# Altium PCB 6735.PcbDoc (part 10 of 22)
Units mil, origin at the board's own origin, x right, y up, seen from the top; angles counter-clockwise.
Board outline 2641.73 x 5165.35 mil, 6 copper layers (Top, Inner Layer 2, Inner Layer 3, Inner Layer 4, Inner Layer 5, Bottom), stack 35.7 mil thick; 1011 components, 790 nets, 4118 pads, 9325 vias.
Unrouted connection lines stored in the file: 4610.
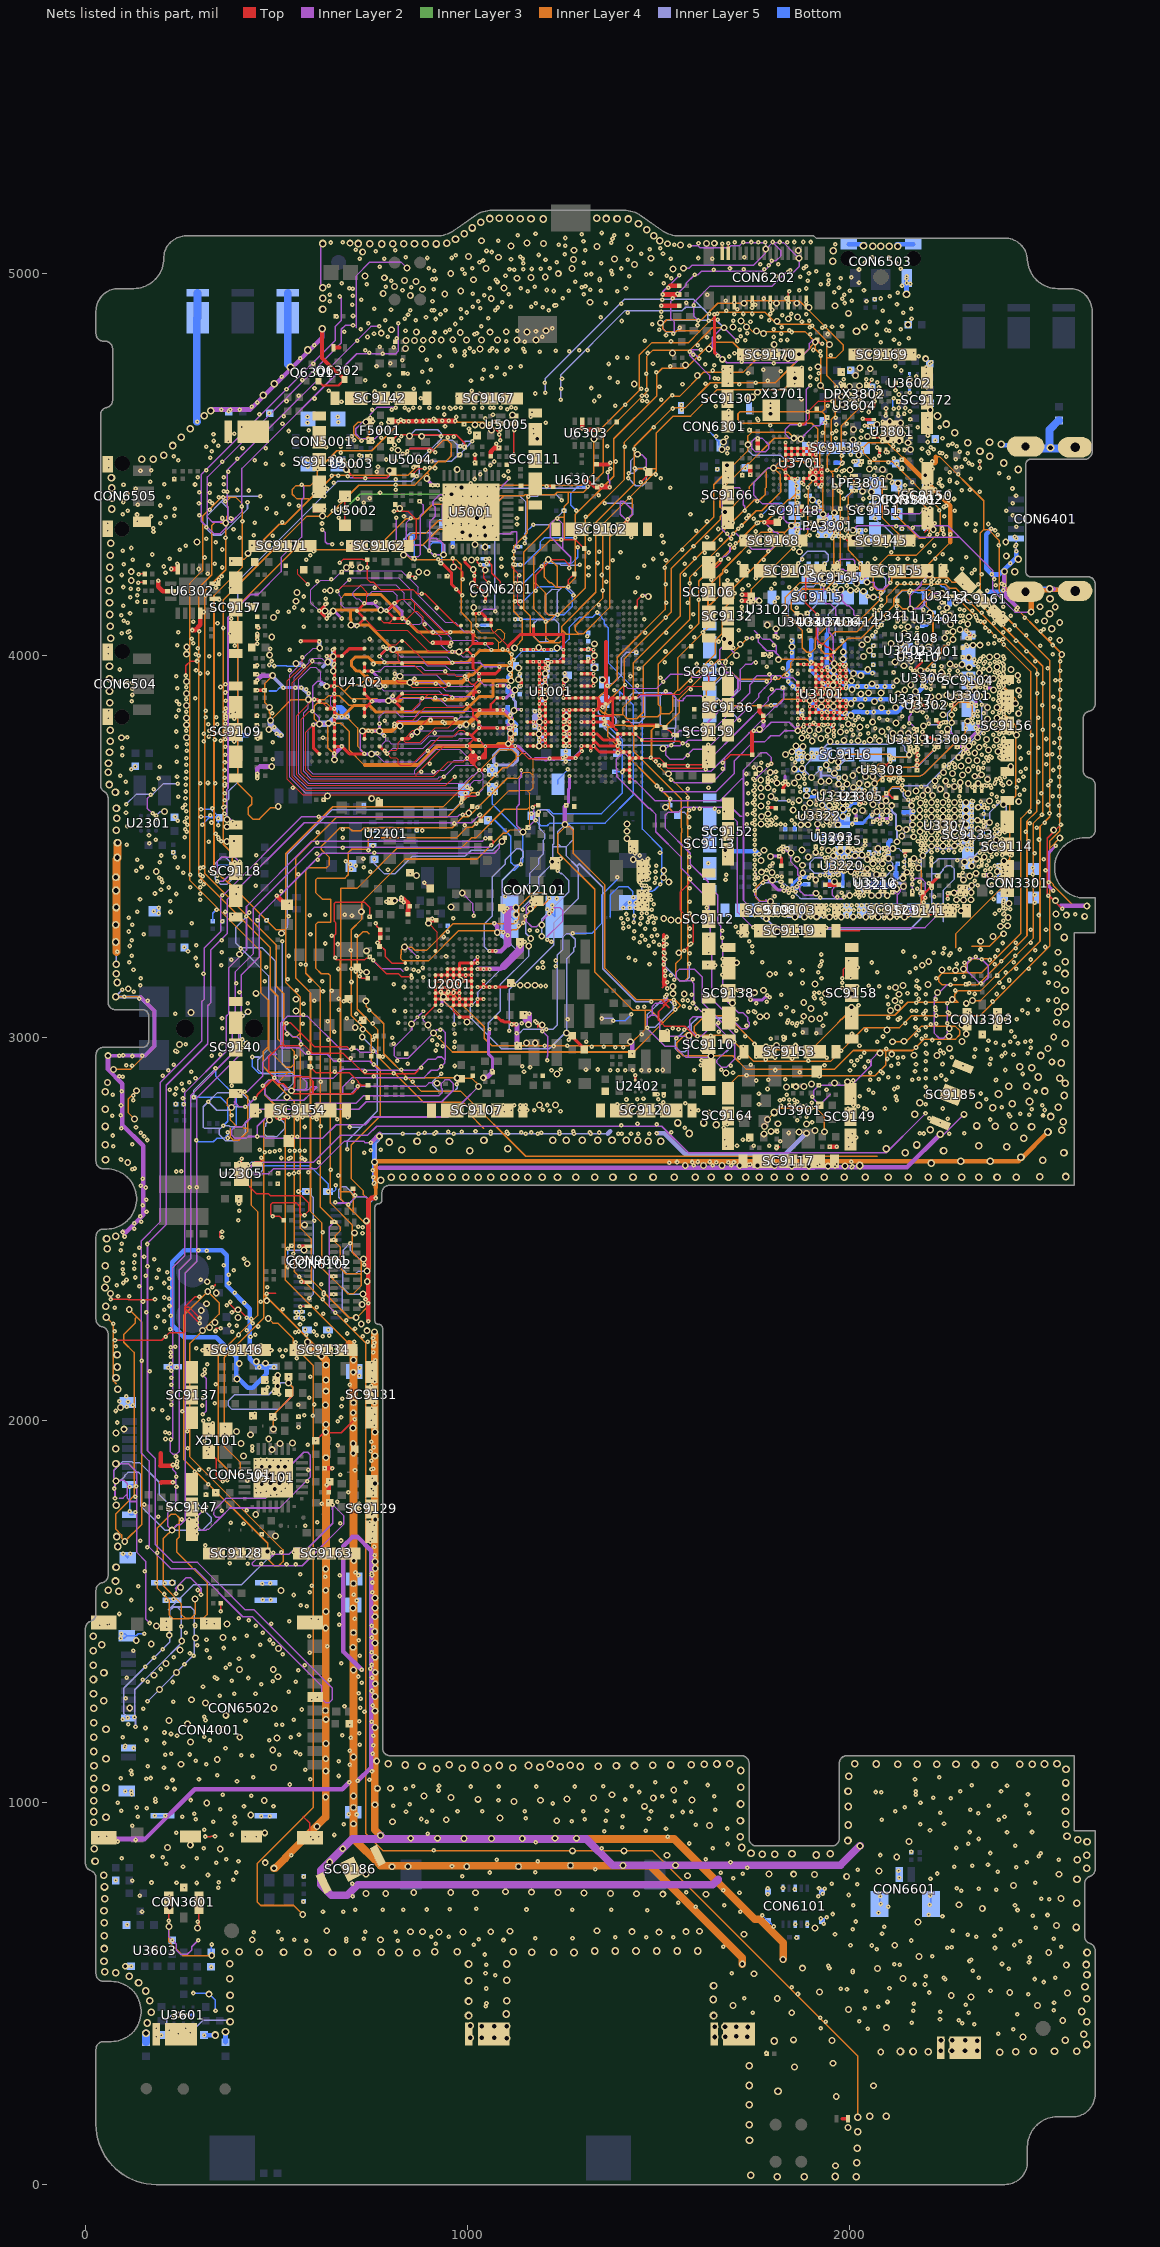
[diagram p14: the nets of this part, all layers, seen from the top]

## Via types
v1: diameter 12, hole 4, Top to Inner Layer 2, 3329 vias
v2: diameter 12, hole 4, Inner Layer 5 to Bottom, 3071 vias
v3: diameter 18, hole 10, Inner Layer 2 to Inner Layer 5, 1928 vias
v4: diameter 10, hole 4, Top to Inner Layer 2, 525 vias
v5: diameter 20, hole 12, Top to Bottom, 472 vias

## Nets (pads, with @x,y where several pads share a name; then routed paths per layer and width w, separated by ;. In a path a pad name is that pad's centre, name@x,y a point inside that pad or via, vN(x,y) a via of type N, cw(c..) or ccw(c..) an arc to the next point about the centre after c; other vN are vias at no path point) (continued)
D_GND: (continued)
  Inner Layer 5 w4: v5(79.09,3107.9) 85.95,3107.9 85.95,3115.49 v2(95.95,3125.49) ; v5(80.31,3193.09) 80.31,3225.09 v2(83.31,3225.09) ; v2(106.31,3611.09) 133.31,3638.09 176.9,3638.09 204.15,3665.34 v2(241.42,3665.34) ; v2(110.95,1221.49) 99.95,1232.49 99.95,1298.6 219.95,1418.6 219.95,1500.94 ; v2(130.95,1197.49) 130.95,1222.49 128.95,1224.49 128.95,1294.72 172.82,1338.59 204.35,1370.12 240.13,1405.91 v3@250.31,1416.09 ; 155.36,2955.09 172.31,2972.04 ; v2(162.31,1264.09) 284.31,1386.09 284.31,1502.3 275.53,1511.09 230.1,1511.09 229.5,1510.49 ; v2(184.64,3581.19) 195.54,3592.09 v3(206.74,3592.09) ; v2(231.3,443.09) 225.13,443.09 212.31,430.27 212.31,413.08 223.3,402.09 279.3,402.09 307.3,430.09 378.3,430.09 v5(378.3,426.09) ; v3(251.92,1422.19) v3@250.31,1416.09 ; v2(283.71,2844.49) 283.71,2863.49 v2(340.31,2920.09) ; v3(366.95,4346.83) 368.95,4344.83 369.31,4345.09 372.31,4348.09 372.31,4386.3 355.26,4403.35 ; v3(369.96,3571.8) 369.96,3620.59 375.15,3625.77 375.15,3645.8 398.95,3669.61 398.95,4195.73 659.31,4456.09 852.31,4456.09 872.95,4476.73 v2(872.95,4509.49) 904.31,4540.85 ; v2@417.13,2816.09 413.13,2820.09 378.37,2820.09 v3(381.73,2818.12) 377.88,2818.12 377.88,2810.7 343.7,2810.7 v2(321.31,2833.09) ; v2(420.81,3318.15) 422.99,3318.59 421.69,3317.28 392.95,3288.54 392.95,3248.31 404.95,3236.31 ; v3(422.94,2984.48) 405.32,3002.1 405.32,3048.86 v3(424.95,3068.48) ; v2(423.95,4401.83) 423.95,4384.17 355.61,4315.83 332.74,4315.83 318.95,4329.62 318.95,4367.04 355.26,4403.35 ; v2(436.31,2950.09) 454.41,2950.09 456.31,2948.19 ; v2(456.95,4416.83) 368.74,4416.83 355.26,4403.35 ; v2(464.31,2875.09) 470.31,2869.09 470.31,2852.09 485.31,2837.09 497.39,2837.09 521.48,2861.18 521.48,2870.09 ; v3(479.71,3807.09) 479.14,3806.71 479.14,3805.53 490.91,3805.53 v2(500.12,3796.33) ; v3(481.19,2784.95) 471.86,2775.62 471.86,2769.81 467.31,2765.26 467.31,2750.14 476.36,2741.09 499.53,2741.09 521.31,2762.88 521.31,2775.84 v2(508.17,2788.98) ; v2(491.79,1652.61) 409.01,1569.83 283.19,1569.83 217.12,1503.76 219.95,1500.94 ; v3(513.14,3273.68) 528.17,3288.7 528.17,3295.67 529.77,3297.27 529.77,3314.67 529.22,3315.22 527.43,3317.01 527.43,3318.01 v2@527.53,3318.01 ; v2(515.1,3252.49) 515.1,3114.08 514.95,3113.94 514.95,2932.62 544.24,2903.33 544.24,2881.91 532.43,2870.09 521.48,2870.09 ; v2(529.72,2448.27) 532.94,2445.05 v3(572.13,2445.05) ; v2(532.01,3318.01) v2@527.53,3318.01 ; v2(579.64,2598.19) 596.31,2581.52 596.31,2329.85 585.43,2318.97 v2(585.31,2319.09) ; v2(684.95,2708.83) 684.95,2730.47 721.31,2766.83 ; v2(690.95,2766.83) 721.31,2766.83 ; v3(708.31,2268.09) 689.89,2268.09 672.08,2285.9 672.08,2350.57 673.6,2352.09 ; v3(724.31,3002.09) 763.95,2962.45 763.95,2809.47 721.31,2766.83 ; v3(725.91,2329.63) 690.33,2329.63 673.6,2346.36 673.6,2352.09 ; v3(727.81,2421.25) 716.81,2421.25 692.25,2445.81 v2(692.25,2463.09) 675.08,2445.92 675.08,2411.09 ; v3(734.82,2521.43) 744.31,2530.92 744.31,2568.09 748.31,2572.09 ; v3(736.3,2390.09) 714.29,2390.09 707.29,2383.09 683.89,2383.09 675.08,2391.9 675.08,2411.09 ; v2(755.95,3467.83) 755.95,3455.45 781.34,3430.06 810.31,3430.06 855.31,3475.06 993.31,3475.06 1009.34,3491.09 1065.21,3491.09 1084.44,3510.32 1085.12,3509.65 1089.35,3513.87 v3(1089.69,3513.53) ; v3(832.31,4263.09) 832.31,4283.09 v2(833.31,4283.09) ; v3(847.52,4574.76) 847.39,4575.11 863.37,4591.09 921.59,4591.09 931.31,4581.36 931.31,4567.85 904.31,4540.85 ; v2(905.31,4509.09) 958.62,4509.09 972.56,4523.03 972.56,4551.97 961.44,4563.09 934.31,4563.09 909.24,4538.02 907.14,4538.02 904.31,4540.85 ; v2(930.31,4409.09) 936.91,4402.49 938.95,4402.49 ; v2(930.64,2906.24) 920.86,2896.46 919.27,2896.46 908.7,2885.88 908.7,2876.77 925.38,2860.09 964.31,2860.09 972.54,2868.32 v3(972.54,2895.04) ; v3(936.9,3107.5) 936.9,3097.07 965.31,3068.66 v2(965.31,3035.09) ; v2(980.06,4527.5) 996.17,4543.61 996.17,4544.78 v2(1012.28,4560.88) 993.45,4560.88 v2(980.06,4547.5) ; v2(982.91,4340.77) 978.22,4336.09 927.31,4336.09 908.31,4317.09 ; v2(982.95,3616.49) 963.86,3597.4 645.77,3597.4 631.48,3583.11 527.43,3479.05 527.43,3332.95 527.53,3332.84 v2@527.53,3318.01 ; v3(1043.31,4336.09) 1043.31,4357.09 1053.31,4367.09 1053.31,4406.09 1085.31,4438.09 1314.31,4438.09 v2(1314.31,4442.68) ; v2(1071.78,4116.16) 1071.31,4114.87 1071.31,4395.3 1094.1,4418.09 1136.53,4418.09 1152.31,4402.3 1152.31,4291.72 1151.03,4294.85 v2(1149.86,4294.71) ; v2(1109.31,3019.09) 1109.31,3127.22 1225.31,3243.22 1225.31,3300.56 1288.95,3364.2 1288.95,3445.45 1285.31,3449.09 ; v2(1127.95,3011.83) 1127.95,3013.09 1135.98,3013.09 1144.98,3022.09 1222.31,3022.09 1234.31,3034.09 v2@1234.31,3184.09 ; v2@1141.25,3452.09 1141.25,3452.53 v2(1138.95,3454.83) ; v2(1144.01,3336.07) 1144.01,3341.09 1185.95,3383.03 1185.95,3420.13 1219.42,3453.6 v3@1219.42,3453.71 ; v2(1158.16,4416.07) 1164.31,4417.09 1182.31,4417.09 1186.31,4421.09 1232.31,4421.09 v2(1246.31,4407.09) ; v3(1159.95,3240.83) 1160.31,3240.47 1160.31,3214.4 1085.31,3139.4 1085.31,3070.29 1053.48,3038.46 1053.48,3007.09 ; v3(1164.95,3259.83) 1164.95,3260.83 1151.95,3273.83 1151.95,3321.04 1177.74,3346.83 1197.16,3346.83 1214.69,3364.35 v2(1213.95,3365.09) ; v2(1171.95,4342.83) 1214.7,4342.83 1236.37,4364.5 1236.62,4364.5 v2(1251.95,4379.83) ; v3(1193.95,3265.83) v3(1193.95,3295.83) 1193.95,3310.88 1264.12,3381.04 1264.12,3412.58 1246.54,3430.16 1242.98,3430.16 v2(1236,3437.13) v3@1219.42,3453.71 ; v2(1202.95,4687.83) 1202.95,4725.15 1410.89,4933.09 1590.45,4933.09 1611.71,4911.83 ; v2(1203.77,4089.21) v2@1203.95,4089.02 ; v3(1210.95,4251.83) 1215.18,4251.83 1223.92,4243.09 1224.44,4243.09 1225.44,4242.09 1225.91,4242.09 1227.61,4240.39 1239.97,4240.39 1243.93,4236.43 1293.16,4236.43 v2(1293.16,4238.23) ; v3(1221.25,3460.92) v3@1222.31,3457.53 ; 1221.44,4173.97 1220.73,4173.97 1203.62,4157.32 1203.62,4115.09 1211.88,4106.83 v2(1234.95,4106.83) 1234.95,4167.61 1241.31,4173.97 1245.88,4178.54 1262.86,4178.54 1277.31,4164.09 1277.31,4163.39 v2(1276.8,4158.33) ; v2(1230.19,3187.79) 1230.03,3187.79 1230.03,3186.09 1232.31,3186.09 v2@1234.31,3184.09 ; v2(1243.95,4669.83) 1243.95,4735.04 1411.75,4902.83 1561.62,4902.83 1570.62,4911.83 1611.71,4911.83 ; v3(1258.95,3012.83) 1256.04,3012.83 v3@1255.37,3013.51 ; v2(1262.31,3049.09) 1261.31,3050.09 v2@1258.95,3050.09 ; v2(1350.96,3050.69) 1350.96,3051.09 1380.31,3051.09 1381.31,3050.09 v2(1381.31,3045.09) ; v3(1352.64,3936.03) 1361.58,3927.09 1379.79,3927.09 1401.31,3948.62 1401.31,3994.09 1416.31,4009.09 v2(1441.31,4009.09) ; v2(1353.95,3865.49) 1360.47,3865.49 1372.56,3877.59 1372.56,3889.89 1363.45,3899 1350.06,3899 1341.95,3890.89 1341.95,3849.49 v2(1355.95,3835.49) 1365.55,3845.09 1378.31,3845.09 1388.08,3835.32 1388.08,3822.89 1379.27,3814.09 1363.35,3814.09 v2(1356.95,3820.49) 1356.95,3811.45 v2(1396.31,3772.09) 1396.31,3766.09 v2(1532.31,3766.09) 1542.31,3776.09 1542.31,3810.09 ; v2(1358.95,4398.83) 1429.31,4398.83 1432.31,4395.83 1432.31,4369.81 1417.03,4354.53 1415.65,4354.53 v2(1403.95,4342.83) ; 1366.49,2749.09 1192.87,2749.09 775.3,2749.09 v3(768.88,2742.68) 768.88,2731.38 760.31,2722.81 760.31,2584.09 748.31,2572.09 ; v2(1419.95,4464.83) 1439.95,4444.83 1456.94,4444.83 1467.43,4455.32 1467.43,4491.83 1465.43,4489.83 1446.31,4489.83 1434.31,4477.83 v2(1420.95,4477.83) 1426.31,4483.19 1426.31,4509.1 v3(1444.2,4526.99) ; v2(1434.31,3303.09) 1434.31,3309.09 1435.31,3310.09 v2(1435.31,3319.09) ; v2(1454.95,3382.49) v2(1454.95,3399.49) ; v2(1479.98,3094.45) 1439.64,3094.45 1353.31,3180.78 1353.31,3394.09 1291.81,3455.59 1285.31,3449.09 ; v2(1516.31,3206.09) 1516.31,3187.75 1554.98,3149.09 1570.57,3149.09 1579.95,3158.47 v2(1579.95,3193.83) ; v2(1518.15,3906.9) 1512.92,3903.09 ; v2(1529.59,3625.13) 1529.59,3614.39 1529.25,3614.05 1529.25,3598.88 1538.04,3590.09 1547.69,3590.09 1547.95,3589.83 1567.57,3589.83 v2(1579.31,3578.09) ; v2(1554.95,4857.83) 1543.95,4846.83 1519.36,4846.83 1510.31,4855.87 1510.31,4870.19 1517.95,4877.83 v2@1627.95,4877.83 ; v2(1618.31,3068.09) 1617.66,3067.43 1623.31,3061.78 1623.31,3054.09 ; v2(1630.23,4876.11) v2@1627.95,4877.83 ; v2(1655.31,3039.09) 1655.31,3051.09 1656.31,3052.09 ; 1657.05,2954.81 1666.95,2954.81 ; v3(1670.31,4858.09) 1650.57,4877.83 1630.23,4877.83 v2@1627.95,4877.83 ; 1676.34,2963.56 1697.31,2984.54 v2(1697.31,2989.56) ; 1676.34,3052.09 1656.31,3052.09 ; v2(1710.65,3830.59) 1704.3,3836.94 1704.3,3838.28 1661.49,3881.09 ; v3(1733.31,4552.09) 1733.31,4537.71 1746.93,4524.09 1819.34,4524.09 1826.34,4517.09 1855.61,4517.09 1862.61,4510.09 v2(1888.3,4510.09) ; 1765.58,3358.09 1764.87,3358.09 1753.65,3369.31 1753.65,3386.59 v2(1772.65,3405.59) 1794.05,3405.59 1797.37,3408.91 v2(1817.67,3408.91) ; v3(1780.43,3418.88) 1781.36,3418.88 v3@1783.01,3417.23 ; v3(1781.4,3311.78) 1808.59,3284.59 2157.65,3284.59 2213.6,3340.53 2213.6,3429.41 ; v2(1782.65,3932.59) 1713.47,3932.59 1706.68,3939.38 ; v3(1791.99,3357.02) v3@1792.8,3357.83 ; v3@1794.65,3358.59 1793.56,3358.59 v3@1792.8,3357.83 ; v2(1807.59,3624.77) 1811.77,3620.59 1824.97,3620.59 1825.43,3620.13 v2(1840.46,3620.13) ; v2(1849.53,3391.68) 1858.44,3382.78 1858.44,3376.76 1869.41,3365.79 1870.25,3365.79 1871.51,3364.53 1873.01,3364.53 1873.95,3363.59 1982.05,3363.59 1991.38,3372.92 v3(1999.69,3372.92) ; v2(1865.17,4242.31) 1871.54,4248.67 1871.54,4255.53 1872.12,4256.12 1889.09,4273.09 1934.4,4273.09 1943.39,4264.1 1943.39,4249.15 v2(1934.31,4240.07) ; v3(1912.98,3316.79) v3@1914.47,3315.59 ; 1921.17,3312.5 1918.3,3312.5 v3@1914.47,3315.59 ; v2(1923.43,3703.69) 1913.19,3693.44 1912.54,3693.44 1900.17,3681.07 v3(1899.65,3681.59) 1883.65,3697.59 1883.65,3712.63 1897.24,3726.22 1898.65,3726.22 1941.03,3768.59 2104.65,3768.59 2111.65,3775.59 2128.94,3775.59 2144.06,3760.47 2144.06,3751.88 v3(2155.25,3740.69) 2150.15,3735.59 2112.36,3735.59 2106.36,3741.59 2002.6,3741.59 1968.18,3707.16 v2(1968.96,3706.38) ; 1924.65,3686.59 1948.65,3686.59 1954.65,3680.59 v2(1970.65,3680.59) ; v2(1932.64,4089.31) v2@1936.75,4088.23 ; v2(1943.11,4172.42) 1965.85,4172.42 1980.56,4157.71 1980.56,4145.29 1962.29,4127.02 1962,4127.02 1943.98,4109 1943.98,4095.45 v2@1936.75,4088.23 ; 1961.65,4051.59 1961.65,4082.09 v3@1965.32,4085.76 ; 1961.65,4089.06 v3@1962.02,4089.06 ; v2(1984.31,4411.09) 1985.53,4411.09 2008.31,4433.87 2008.31,4446.3 1989.53,4465.09 v2(1986.31,4465.09) ; 2010.34,3410.44 2022.42,3398.36 2027.69,3393.09 2102.83,3393.09 2117.7,3407.96 2132.99,3423.25 2144.69,3434.95 2144.69,3479.88 ; v3(2045.65,3442.59) v3@2045.65,3440.98 ; v3(2060.65,3455.59) 2044.32,3471.92 1908.7,3471.92 1895.65,3458.87 1895.65,3442.31 1907.37,3430.59 1967.38,3430.59 1974.38,3437.59 2031.26,3437.59 2034.65,3440.98 v3@2045.65,3440.98 ; v3(2061.65,4153.09) 2076.33,4153.09 2091.56,4168.32 2091.56,4180.5 2093.87,4182.8 2093.87,4201.61 v2(2080.57,4214.91) ; v2(2064.62,3650.43) 2064.62,3638.85 v3(2076.45,3627.03) 2076.45,3616.03 2079.59,3612.89 2086.36,3612.89 v3(2094.14,3620.67) ; v2(2065.81,4359.12) 2082.66,4342.28 2087.44,4342.28 2116.31,4313.4 2116.31,4278.09 ; v3@2104.87,3464.35 2112.74,3456.49 2112.74,3441.66 2091.02,3419.94 2052.58,3419.94 2045.65,3426.87 v3@2045.65,3440.98 ; v2@2104.87,3487.81 2104.87,3488.31 v3(2112.37,3495.81) ; v3(2109.65,3607.59) 2098.65,3618.59 2098.65,3638.18 2098.95,3638.48 2098.95,3640 2100.16,3641.21 2100.16,3641.73 2100.57,3642.14 2100.57,3642.44 2100.87,3642.74 2100.87,3643 2101.18,3643.31 2101.18,3643.66 2101.67,3644.15 2101.67,3644.89 2110.37,3653.59 2126.94,3653.59 ; v2(2132.9,4016.48) 2133.43,4016.48 2133.43,3999.71 v3(2133.96,3999.71) ; v3(2135.65,3528.59) 2157.65,3550.59 2157.65,3615.15 2139.65,3633.15 2139.65,3640.88 2126.94,3653.59 ; v3(2144.72,4096.17) 2122.81,4118.07 2122.81,4154.93 2138.29,4170.41 2151.73,4170.41 2155.81,4166.33 v2(2155.81,4165.65) ; v2(2149.46,3999.07) 2148.89,3998.5 v3@2160.65,3986.74 ; v2(2156.12,4014.27) 2156.12,4004.89 2160.65,4000.36 v3@2160.65,3986.74 ; 2177.36,3340.1 2152.85,3315.59 2073.67,3315.59 2025.65,3315.59 v3@1914.47,3315.59 ; v2(2183.65,3378.59) 2183.65,3387.59 2186.4,3390.34 2186.4,3470.34 2218.65,3502.59 2221.66,3499.59 2221.66,3499.27 2225.34,3495.59 2258.65,3495.59 2270.15,3495.59 2282.65,3508.09 2315.47,3508.09 2356.9,3549.52 2356.9,3555.31 v3(2365.38,3563.8) 2365.38,3589.87 2397.1,3621.59 2406.21,3621.59 2408.69,3619.11 2408.69,3559.18 2349.05,3499.54 2349.05,3499.07 2323.89,3473.91 2312.37,3473.91 2306.68,3468.22 2231.07,3468.22 2213.6,3450.75 2213.6,3429.41 ; v3(2203.65,3648.59) 2203.65,3662.77 ; v2(2206.6,3821.58) 2206.6,3819.59 2229.94,3819.59 2233.65,3815.87 v2(2233.65,3814.59) ; 2244.72,3303.34 2244.72,3386.83 2273.65,3415.76 2273.65,3441.8 2264.87,3450.59 2252.44,3450.59 2243.65,3441.8 2243.65,3438.38 2234.91,3429.63 2230.86,3429.63 2230.63,3429.41 2213.6,3429.41 ; v3@2301.95,3355.49 2301.95,3380.45 2320.93,3399.42 v2(2334.8,3399.42) ; v3(2333.65,3785.59) 2344.65,3796.59 v2@2344.65,3803.77 ; v3(2339.81,3894.34) 2339.81,3882.65 2345.15,3877.3 2345.15,3817.15 2344.65,3816.65 v2@2344.65,3803.77 ; v2(2435.31,4273.09) v2(2435.31,4290.09) ; 219.95,1500.94 229.5,1510.49 ; 229.5,1510.49 241.13,1510.49 250.31,1501.3 v3@250.31,1416.09 ; v2(321.31,2833.09) 345.31,2857.09 407.31,2857.09 430.31,2834.09 430.31,2789.97 418.31,2777.97 418.31,2775.89 ; v2(321.31,2833.09) 308.31,2820.09 308.31,2766.09 310.31,2764.09 354.31,2764.09 ; 354.31,2764.09 v2(360.31,2770.09) 375.31,2770.09 378.31,2767.09 409.52,2767.09 418.31,2775.89 ; 354.31,2764.09 349.58,2759.35 349.58,2748.04 366.52,2731.09 399.41,2731.09 418.31,2750 418.31,2775.89 ; 404.95,3236.31 461.45,3236.31 496.95,3200.8 496.95,2906.09 ; 404.95,3236.31 478.95,3162.31 478.95,2970.83 456.31,2948.19 ; 456.31,2948.19 450.95,2942.83 450.95,2917.62 461.74,2906.83 496.21,2906.83 496.95,2906.09 ; 496.95,2906.09 496.95,2894.62 521.48,2870.09 ; 673.6,2352.09 673.6,2409.61 675.08,2411.09 ; 708.15,2584.09 733.94,2584.09 745.94,2572.09 748.31,2572.09 ; 708.15,2584.09 682.15,2610.09 670.24,2610.09 662.95,2602.8 662.95,2583.23 678.09,2568.09 679.79,2568.09 685.97,2561.91 v2(687.31,2563.25) 708.15,2584.09 ; v2(833.31,4283.09) 842.31,4283.09 848.31,4289.09 884.31,4289.09 v2(899.31,4274.09) ; v2(833.31,4283.09) 833.31,4305.66 849.74,4322.09 903.31,4322.09 908.31,4317.09 ; v2(899.31,4274.09) 909.29,4264.11 v3(936.78,4264.11) 939.7,4264.11 939.7,4289.79 930.4,4299.09 899.31,4299.09 ; v2(899.31,4274.09) 899.31,4299.09 ; 899.31,4299.09 899.31,4308.09 908.31,4317.09 ; 938.95,4402.49 964.95,4402.49 984.13,4421.67 v3(984.13,4440.49) 952.92,4440.49 938.95,4426.52 938.95,4402.49 ; 1053.48,3007.09 1088.74,2971.83 1213.69,2971.83 1222.79,2980.93 v3@1255.37,3013.51 ; 1053.48,3007.09 1006.31,3054.26 1006.31,3080.86 1025.95,3100.5 1025.95,3118.74 1127.95,3220.74 1127.95,3229.83 1101.01,3256.77 1096.25,3256.77 ; 1089.95,3372.09 1089.95,3412.15 1130.63,3452.83 1136.95,3452.83 v2(1138.95,3454.83) ; 1089.95,3372.09 1089.95,3288.23 v3(1077.37,3275.65) 1096.25,3256.77 ; 1089.95,3372.09 1130.18,3372.09 1161.95,3403.86 1161.95,3430.48 1186.31,3454.84 1186.31,3469.88 1198.31,3481.88 1198.31,3517.72 1201.31,3520.72 1201.31,3534.65 1187.31,3548.65 1187.31,3576.09 1185.31,3578.09 v2(1185.31,3591.09) 1190.97,3596.75 1206.33,3596.75 1225.31,3577.76 1225.31,3508.09 1222.31,3505.09 1222.31,3500.09 ; 1096.25,3256.77 1096.25,3241.88 1084.47,3230.09 1052.58,3230.09 1042.92,3239.75 1042.92,3297.38 1064.31,3318.77 1064.31,3420.98 1098.31,3454.98 1098.31,3465.7 1127.7,3495.09 1137.58,3495.09 1145.31,3487.36 1145.31,3473.98 1138.95,3467.62 v2(1138.95,3454.83) ; 1203.95,4037.11 v2@1203.95,4089.02 ; 1203.95,4037.11 1226.32,4037.11 1238.3,4049.09 1238.3,4084.09 1228.28,4094.11 v2@1207.08,4094.11 ; 1203.95,4037.11 1186.12,4037.11 1172.95,4050.27 1172.95,4084.7 1182.36,4094.11 v2@1207.08,4094.11 ; v2@1203.95,4089.02 1203.95,4090.98 v2@1207.08,4094.11 ; v3@1219.42,3453.71 1218.95,3454.17 v3@1222.31,3457.53 ; v3@1219.42,3453.71 1222.31,3456.6 v3@1222.31,3457.53 ; v3@1222.31,3457.53 1222.31,3500.09 ; 1222.31,3500.09 1236,3500.09 1236.26,3499.83 1244.99,3499.83 ; v2@1234.31,3184.09 1234.31,3217.16 1249.31,3232.16 1249.31,3264.06 1257.34,3272.09 1267.28,3272.09 1281.31,3258.06 1281.31,3238.79 1277.56,3235.04 1277.56,3226.19 1258.95,3207.58 v2@1258.95,3050.09 ; 1244.99,3499.83 1235.95,3508.87 1235.95,3539.72 v3(1254.31,3558.09) 1265.31,3558.09 1275.95,3547.45 1275.95,3518.87 1256.91,3499.83 ; 1244.99,3499.83 1256.91,3499.83 ; v3@1255.37,3013.51 1258.95,3017.09 v2@1258.95,3050.09 ; 1256.91,3499.83 1258.31,3498.43 1258.31,3476.09 1285.31,3449.09 ; 1462.31,3903.09 1463.31,3902.09 1463.31,3838.09 1450.31,3825.09 1426.31,3825.09 1415.31,3836.09 1415.31,3886.09 1432.31,3903.09 1462.31,3903.09 ; 1462.31,3903.09 1512.92,3903.09 ; 1479.77,3070.63 1469.45,3060.32 v2(1469.45,3026.05) 1471.49,3028.09 1490.46,3028.09 1506.39,3044.01 ; 1479.77,3070.63 1503.64,3094.51 1503.74,3094.51 v2(1517.31,3108.09) 1537.31,3088.09 1537.31,3075.09 1506.39,3044.16 1506.39,3044.01 ; 1479.77,3070.63 1506.39,3044.01 ; 1512.92,3903.09 1531.53,3903.09 1544.31,3890.3 1544.31,3812.09 1542.31,3810.09 ; 1512.92,3903.09 1503.31,3896.09 1503.31,3822.09 1515.31,3810.09 1542.31,3810.09 ; 1603.31,3054.09 1585.31,3036.09 1585.31,2980.09 1569.31,2964.09 1551,2964.09 1543,2972.09 1543,2994.7 1602.39,3054.09 1603.31,3054.09 ; 1603.31,3054.09 1623.31,3054.09 ; 1611.71,4911.83 1616,4907.54 1616.08,4907.54 1627.95,4895.66 v2@1627.95,4877.83 ; 1623.31,3054.09 1634.31,3054.09 1636.31,3052.09 1656.31,3052.09 ; 1661.49,3881.09 1680.83,3881.09 1706.68,3906.93 1706.68,3939.38 ; 1661.49,3881.09 1653.99,3888.59 1649.12,3888.59 1648.24,3887.71 1647.37,3888.59 1630.44,3888.59 1624.15,3894.88 1624.15,3909.8 1632.94,3918.59 1640.39,3918.59 1677.89,3956.09 1689.97,3956.09 1706.68,3939.38 ; v3@1792.8,3357.83 1803.84,3346.78 1813.84,3336.78 v2(1814.65,3337.59) 1836.65,3315.59 v3@1914.47,3315.59 ; v3@1910.65,4086.09 v3(1916.48,4085.83) v3@1916.48,4086.09 ; v3@1910.65,4086.09 1850.6,4086.09 1838.45,4098.24 1838.45,4141.6 1877.94,4181.09 1904.9,4181.09 1911.62,4187.81 v2(1924.39,4187.81) 1924.39,4145.68 1893.88,4115.17 1893.88,4102.87 v3@1910.65,4086.09 ; v3@1910.65,4086.09 v3@1916.48,4086.09 ; v3@1916.48,4086.09 1916.48,4087.03 1936.75,4087.03 v2@1936.75,4088.23 ; v2@1936.75,4088.23 1948.5,4088.23 1953.8,4093.53 1957.54,4093.53 v3@1962.02,4089.06 ; v3@1962.02,4089.06 v3@1965.32,4085.76 ; v3@1962.02,4089.06 1962.36,4089.06 v3@1965.49,4085.92 ; v3@1965.32,4085.76 v3@1965.49,4085.92 ; v3@1965.32,4085.76 v3(1970.49,4086.89) v3@1965.49,4085.92 ; 2126.94,3653.59 2132.83,3659.48 2200.37,3659.48 2203.65,3662.77 ; v2@2155.81,4163.89 2155.81,4158.43 2158.31,4155.93 2158.31,4123.03 v3(2158.56,4122.5) 2158.56,4123.03 2185.52,4123.03 2194.13,4131.64 2194.13,4162.76 2185.49,4171.39 2168.77,4171.39 2166.03,4168.65 ; v2@2155.81,4163.89 v2(2155.81,4165.65) ; v2@2155.81,4163.89 2160.57,4168.65 2166.03,4168.65 ; v2(2155.81,4165.65) 2161.64,4171.48 2163.2,4171.48 2166.03,4168.65 ; v3@2160.65,3986.74 2161.23,3986.16 v3(2160.65,3985.59) v3@2160.65,3986.74 ; 2203.65,3662.77 v2@2344.65,3803.77 ; v3@74.31,1847.09 74.31,1868.3 88.84,1882.83 89.03,1882.83 97.03,1890.83 122.05,1890.83 124.05,1888.83 141.71,1888.83 192.95,1837.59 192.95,1805.18 215.3,1782.83 291.56,1782.83 328.95,1745.44 328.95,1734.52 306.52,1712.09 v3(226.31,1712.09) 208.17,1712.09 145.31,1774.94 145.31,1856.94 139.17,1863.09 111.21,1863.09 102.31,1854.19 102.31,1852.09 91.31,1841.09 v3(80.31,1841.09) v3@74.31,1847.09 ; v2(327.09,3435.69) 327.09,3444.18 355,3472.09 366.91,3472.09 388.31,3450.68 v2(388.31,3439.09) 388.31,3419.49 370.31,3401.49 354.09,3401.49 339.7,3415.88 339.7,3423.09 v2(327.09,3435.69) ; 373.31,2038.38 373.31,2049.78 389.62,2066.09 479.55,2066.09 v3(502.95,2089.49) 510.95,2097.49 v3(530.95,2097.49) 542.31,2086.13 542.31,2064.88 505.53,2028.09 383.6,2028.09 373.31,2038.38 ; v2@425.31,2662.09 v2(425.31,2666.09) 434.31,2675.09 454.76,2675.09 463.55,2666.3 463.55,2653.88 454.76,2645.09 442.31,2645.09 v2@425.31,2662.09
  Inner Layer 5 w6: v3@2063.65,3427.59 v3(2069.65,3427.59) ; v3(2109.65,3607.59) 2109.65,3594.03 2120.65,3583.03 2120.65,3546.35 2123.07,3543.93 v3(2123.07,3513.14) v3@2124.86,3511.36 ; v3@2110.87,3497.37 2112.37,3495.87 v3(2112.37,3495.81)
  Inner Layer 5 w8: v5(79.09,3107.9) 85.95,3107.49 142.27,3107.49 179.35,3070.41 179.35,2978.83 155.61,2955.09 155.36,2955.09 v2(98.31,2955.09) ; v3(736.3,2390.09) 743.31,2397.1 ; v3(1106.25,3769.53) 1106.25,3759.81 1100.93,3754.49 1082.91,3754.49 1068.24,3739.82 1068.24,3721.16 v2(1075.31,3714.09) 1118.55,3714.09 1129.95,3725.49 1129.95,3745.83 ; v3(1121.21,3856.64) 1124.95,3859.49 1124.95,3880.34 1119.95,3885.34 1119.95,3906.49 v3(1123.95,3910.49) ; v2(1835.65,3495.59) 1845.65,3485.59 v3(1845.65,3483.59) ; v3(1886.65,3633.59) v3(1886.65,3633.59) 1886.7,3649.61 v2(1886.76,3649.61) ; v2(1923.43,3703.69) 1924.65,3703.69 1924.65,3686.59 v3(1924.65,3670.59) ; v3(1938.25,3713.88) 1936.78,3712.41 1947.13,3702.06 v2(1945.65,3700.59) ; v3(1970.65,3664.59) v2(1970.65,3680.59) ; v3@1975.65,3485.59 v3(1975.65,3488.59) ; v2(2024.55,3649.61) 2024.6,3649.61 2024.6,3665.59 v3(2024.65,3665.59) ; v3(2024.65,3700.59) v2(2040.65,3700.59) ; v2(2048.38,3481.48) v2(2048.38,3481.48) 2062.65,3481.53 v2(2062.65,3481.59) 2061.9,3482.34 2074.4,3494.84 v3(2073.65,3495.59) ; v3(2060.65,3610.59) v2(2060.65,3625.75) ; v2(2120.64,3405.02) 2131.45,3405.02 v3(2140.64,3395.82)
  Inner Layer 5 w10: v3(489.82,3947.92) 488.76,3946.86 508.31,3927.31 508.31,3926.94 517.1,3918.15 517.48,3918.15 518.42,3917.2 v2(517.83,3916.61) ; v2(549.33,3916.61) v2(565.07,3916.61) 565.33,3916.87 583.08,3899.11 v3(583.08,3885.11) ; v3(550.95,3979.49) 564.95,3979.49 v2(571.45,3972.99) ; v2(611.76,4036.71) 612.42,4036.71 612.42,4020.11 v3(613.08,4020.11) ; 616.39,3925.85 625.34,3925.85 v3(631.08,3920.11) ; 621.55,3971.31 621.73,3971.12 v3@633.9,3983.29 ; v2(637.36,4106.39) v3(648.08,4117.11) ; v2(647.36,4016.02) 647.72,4016.02 647.72,3998.11 v3(648.08,3998.11) ; v3(648.32,3960.04) 649.07,3960.04 v2@649.07,3975.01 ; v2(650.79,3744.07) 651.03,3744.07 651.03,3727.69 v3(651.27,3727.69) ; v3(695.08,4080.11) 695.08,4080.02 711.96,4080.02 v2(711.96,4079.93) ; v3@725.08,3803.16 v2(740.11,3803.21) ; v3(748.08,3743.11) 748.08,3743.9 763.01,3743.9 v2(763.01,3744.7) ; v3(769.08,3803.11) v2(781.4,3790.79) ; v3(769.08,3920.11) v2(784.08,3919.95) ; v3(793.08,3882.11) 792.79,3882.41 804.6,3894.22 v2(804.31,3894.52) ; v3(805.08,4016.11) 806.91,4017.94 v2(821.77,4017.94) ; v2(808.03,3815.91) 808.03,3816.01 823.08,3816.01 v3(823.08,3816.11) ; v2(809.33,3952.25) v3(823.08,3946.11) ; v3(849.08,3930.11) 849.75,3929.44 860.29,3939.98 v2(860.96,3939.32) ; v3(867.08,3800.11) v2(878.82,3811.85) ; v2(959.8,4010.11) v3(977.08,4010.11) ; v2(980.03,3814.94) 985.2,3820.11 v3(996.08,3820.11) ; v3(1114.1,3827.33) 1113.6,3826.83 1124.45,3815.98 v2(1123.95,3815.49) ; v2@1135.95,3920.02 v2(1135.95,3920.49) ; v2(1201.95,3937.49) 1201.95,3922.23 1202.51,3921.67 v3(1203.08,3921.1) ; v3(1203.08,3953.1) 1209.95,3959.97 v2(1209.95,3967.49) 1209.95,3978.7 1210.17,3978.7 v2(1210.17,3979.56) ; v3@633.9,3983.29 633.83,3983.36 648.33,3997.86 v3(648.08,3998.11) ; v3@633.9,3983.29 v3(634.08,3983.11) 636.18,3985.2 647.71,3973.66 v2@649.07,3975.01 ; v3(648.08,3998.11) 648.94,3998.11 648.94,3975.76 v2@649.07,3975.76 ; v2@649.07,3975.01 v2(649.81,3975.76) v2@649.07,3975.76 ; v2@649.07,3975.01 v2@649.07,3975.76
  Inner Layer 5 w12: v2(1111.95,3811.49) 1119.95,3811.49 v2(1123.95,3815.49) ; v3(1112.08,3796.1) 1113.89,3796.1 1113.89,3781.26 v2(1115.7,3781.26) ; v3(1121.21,3856.64) 1121.65,3856.19 1113.95,3848.49 v2(1111.93,3844.8) 1111.1,3845.63 1109.95,3844.49 1109.95,3796.1 1109.95,3773.23 v3(1106.25,3769.53) 1129.95,3745.83 ; v2(1174.95,3815.49) 1174.95,3842.49 v2(1187.95,3842.49) v3(1187.95,3826.83) 1187.45,3826.83 1187.45,3810.49 v2(1186.95,3810.49) v3(1186.95,3795.49) v2(1186.95,3779.49) 1187.01,3779.49 1187.01,3764.1 v3(1187.08,3764.1) ; v2(1201.95,3905.49) v2@1202.51,3905.49 ; v3(1203.08,3890.1) 1202.52,3890.1 v2@1202.52,3905.49 ; v3(1203.08,3921.1) v3@1202.51,3920.54 ; v3(1203.08,3953.1) 1203.08,3925.58 1202.51,3925.01 1202.51,3921.67 v3@1202.51,3920.54 ; v2(1254.1,3953.51) 1255.05,3953.51 1255.05,3937.1 v3(1256.08,3937.1) ; 1366.49,2749.09 1373.23,2755.83 ; v2(1494.81,2750.95) 1514.04,2750.95 1569.69,2695.3 1831.06,2695.3 v3(1886.31,2750.56) ; v2@1202.51,3905.49 v3@1202.51,3920.54
  Inner Layer 5 w15: v3(483.95,3830.49) 483.95,3819.89 488.23,3815.61 v2(511.65,3792.2) ; v3(636.08,3823.11) 636.61,3822.59 654.54,3840.52 v2(655.06,3840) v2(670.06,3840) v2(685.06,3840)
  Inner Layer 5 w18: v3(612.08,3821.11) 612.08,3822.11 636.08,3822.11 v3(636.08,3823.11)
  Bottom w4: R3627.2@78.95,795.49 v2(78.95,795.73) ; v2(92.31,1429.09) 101.75,1429.09 CON6502.11@108.42,1435.76 ; v2(93.31,1441.09) 103.08,1441.09 CON6502.11@108.42,1435.76 ; v2(97.31,1217.09) 101.22,1220.99 CON6502.9@113.14,1220.99 ; v2(98.31,1650.09) 100.65,1650.09 CON6501.12@110.58,1640.16 110.58,1643.36 v2(117.31,1650.09) ; v2(104.31,1029.09) 105.07,1029.85 CON6502.12@108.42,1029.85 119.55,1029.85 v2(120.31,1029.09) ; R3624.2@107.3,679.09 108.3,680.09 v2(109.31,680.09) ; v2(110.95,1221.49) 112.65,1221.49 CON6502.9@113.14,1220.99 ; v2(111.31,2048.09) CON6501.11@110.58,2047.35 ; v2(116.31,1761.09) CON6501.5@115.3,1760.08 ; v2(116.31,1826.09) 116.31,1830.29 CON6501.9@115.3,1831.3 ; v2(120.31,3703.09) 127.71,3710.49 C2320.2@129.95,3710.49 v2(130.31,3710.13) ; v2(123.31,2039.09) 116.34,2046.07 CON6501.11@110.58,2046.07 ; v2(128.31,1223.09) 115.24,1223.09 CON6502.9@113.14,1220.99 ; v2(130.31,1759.09) 123.79,1752.56 CON6501.5@115.3,1752.56 CON6501.5@115.3,1760.08 ; v2(132.31,1827.09) 128.1,1831.3 CON6501.9@115.3,1831.3 ; v2(153.31,1441.09) 138.41,1441.09 133.07,1435.76 CON6502.11@108.42,1435.76 ; v2(178.31,3331.09) L6002.1@180.95,3331.08 ; v2(180.92,964.69) CON6502.14@201.33,964.69 v2(208.71,964.69) ; v2(191.31,3326.09) 186.32,3331.08 L6002.1@180.95,3331.08 ; v2(191.31,3340.09) 189.96,3340.09 L6002.1@180.95,3331.08 ; CON6501.14@203.49,1575 205.4,1575 v2(207.31,1573.09) ; v2(211.31,1529.09) 226.11,1529.09 CON6502.13@226.33,1528.87 228.56,1531.09 v2(230.31,1531.09) ; v2(216.31,2137.09) 218.4,2139.18 CON6501.13@228.49,2139.18 ; v2(229.35,3486.09) C2323.2@229.95,3485.49 ; v2(231.3,443.09) 231.3,443.25 U3601.6@231.43,443.38 ; C2322.2@232.35,3578.09 C2322.2@232.95,3577.49 ; v2(234.31,3579.09) 232.95,3577.73 C2322.2@232.95,3577.49 ; v2(236.35,2827.09) C6021.1@236.95,2826.49 ; v2(241.31,3568.09) 241.31,3569.13 C2322.2@232.95,3577.49 ; U3601.9@256.43,443.38 256.3,443.25 256.33,443.38 256.38,443.54 256.44,443.54 260.91,443.38 262.31,443.33 v2(262.3,443.09) ; C6019.2@256.95,2826.49 v2(256.95,2826.73) ; v2(258.95,3236.73) R6012.1@258.95,3236.49 266.31,3229.13 v2(268.28,3226.98) ; v2(282.3,501.09) 321.3,501.09 339.3,483.09 339.3,455.09 v2(340.3,455.09) ; v2(283.71,2844.49) R6029.2@283.95,2844.49 353.66,2844.49 372.31,2825.83 372.31,2782.09 v2(360.31,2770.09) ; v2(290.31,2732.09) 294.31,2728.09 334.35,2728.09 343.35,2737.09 362.63,2737.09 373.31,2747.77 373.31,2749.99 374.31,2750.99 374.31,2752.13 394.31,2772.13 394.31,2846.64 340.31,2900.64 v2(340.31,2920.09) ; v2(302.31,3579.09) LED2302.2@347.79,3579.09 ; v2(302.31,3598.09) 328.79,3598.09 LED2302.2@347.79,3579.09 ; v2(305.31,3558.09) 323.08,3575.86 347.31,3575.86 LED2302.2@348.08,3575.86 ; v2(327.09,3435.69) 327.09,3443.69 335.15,3451.75 375.65,3451.75 v2(388.31,3439.09) ; L3605.2@328.31,570.09 v2(329.31,569.09) ; C3601.1@329.53,607.69 329.53,627.31 v2(330.31,628.09) ; C6007.2@333.31,3305.65 333.31,3326.19 v2(342.95,3335.83) ; v2(347.31,3556.09) 347.31,3572.16 LED2302.2@351.02,3575.86 ; v2(347.31,3575.09) LED2302.2@348.08,3575.86 ; v2(357.92,3305.59) 357.98,3305.65 R6007.2@358.31,3305.65 ; v2(384.71,3322.3) 384.71,3322.45 v2@385.81,3323.56 ; v2(420.81,3318.15) 420.81,3323.56 428.31,3323.56 v2(428.31,3328.15) ; v2(425.31,2666.09) 586.38,2666.09 634.96,2617.51 v2(634.96,2598.19) 650.21,2598.19 654.31,2602.29 v2(654.31,2614.09) ; v2(436.31,2950.09) 436.31,2925.09 453.31,2908.09 539.22,2908.09 545.31,2914.18 545.31,2945.09 v2(550.31,2950.09) ; v2(451.16,3307.47) R6006.2@451.31,3307.49 ; v2(454.31,2138.09) 455.39,2139.17 CON6501.16@473.57,2139.18 492.23,2139.18 v2(493.31,2138.09) ; v2(460.31,963.09) 461.92,964.69 CON6502.15@471.41,964.69 480.71,964.69 v2(482.31,963.09) ; v2(462.31,1572.09) 465.23,1575 CON6501.15@473.57,1575 481.4,1575 v2(483.31,1573.09) ; v2(464.31,1530.09) 470.19,1530.09 CON6502.16@471.41,1528.87 472.63,1530.09 v2(485.31,1530.09) ; v2(473.66,3307.36) C6008.2@473.81,3307.49 ; v2@480.35,3973.56 525.62,3973.56 526.19,3972.99 v2(571.45,3972.99) ; v2(480.33,4634.09) L5004.2@482.31,4634.09 ; 480.71,3907.63 499.54,3907.63 508.53,3916.61 v2(517.83,3916.61) ; v2@505.88,3796.33 507.52,3796.33 v2(511.65,3792.2) ; v2(529.54,2400.68) 529.54,2420.39 529.72,2420.57 v2(529.72,2448.27) ; v2(550.31,2268.09) 558.47,2268.09 CON9001.40@559.07,2267.48 559.68,2268.09 v2(566.31,2268.09) ; v2(551.31,2282.09) 552.45,2283.23 CON9001.38@559.07,2283.23 v2(566.17,2283.23) ; v2(557.42,2598.19) v2(579.64,2598.19) ; v2(570.31,740.09) C6023.1@571.31,741.09 ; v2(571.31,805.01) C6024.2@571.31,806.09 ; v2(575.31,2237.09) 578.54,2237.09 CON9001.44@579.65,2235.99 ; CON5001.5@580.31,4495.09 580.31,4501.03 CON5001.5@581.93,4501.03 ; v2(580.95,4609.49) 580.95,4618.16 581.93,4619.14 581.93,4624.51 v2(580.95,4625.49) ; v2(581.31,4494.09) 581.31,4500.42 CON5001.5@581.93,4501.03 ; v2(634.86,2236.09) CON9001.43@634.96,2235.99 ; v2(660.58,4624.85) 660.67,4624.85 CON5001.4@660.67,4619.15 660.95,4618.86 v2(660.95,4610.49) ; v2(662.51,4515) CON5001.6@667.09,4505.86 ; v2(675.31,4512.49) 674.52,4513.28 CON5001.6@667.09,4505.86 ; v2(689.31,969.09) 694.36,974.14 CON6502.18@700.54,974.14 704.26,974.14 v2(710.31,968.09) ; v2(692.95,3454.83) C2411.2@694.91,3452.87 ; CON6502.17@700.54,1516.47 700.54,1518.32 v2(710.31,1528.09) ; CON6501.18@702.7,1584.45 712.34,1594.09 v2(714.31,1594.09) ; v2(706.94,3450.07) 700.31,3445.09 695.31,3450.09 C2411.2@694.9,3450.09 ; v2(716.31,2116.09) 705.63,2126.78 CON6501.17@702.7,2126.78 713.02,2137.09 v2(717.31,2137.09) ; R2417.1@728.31,3609.09 R2417.1@728.31,3610.09 ; v2(751.31,3544.09) U2401.3@751.24,3544.09 ; v2(752.31,3503.09) 752.31,3503.38 U2401.1@751.11,3504.58 ; C2402.2@756.31,3467.09 C2402.2@756.31,3467.47 ; v2(833.31,4283.09) 833.31,4304.92 844.91,4316.5 845.49,4317.09 859.14,4317.09 860.31,4315.92 860.31,4254.09 v2(861.31,4253.09) ; R2406.1@866.95,3542.86 R2406.1@867.2,3543.11 ; v2(899.31,4274.09) 899.31,4287.09 907.31,4295.09 929.31,4295.09 932.31,4292.09 932.31,4246.09 v2(928.31,4242.09) ; C6204.1@934.95,4347.99 935.45,4347.99 936.95,4346.49 939.37,4344.09 v2(942.17,4340.6) ; v2(948.31,3278.09) C2054.2@948.31,3293.09 ; C5014.2@979.38,4353.98 C5014.2@981.95,4350.49 ; v2(982.91,4340.77) 982.95,4337.49 C6201.2@982.95,4327.99 ; v2(994.31,3640.09) D2103.A@994.31,3642.89 ; v2(998.78,3656.09) D2103.A@989.95,3647.26 ; v2(1024.31,4080.09) 1030.66,4080.09 1030.83,4079.91 CON6201.17@1046.63,4079.91 ; v2(1032.95,4237.83) 1031.39,4237.39 CON6201.27@1046.63,4237.39 ; C6203.2@1038.72,4413.31 1038.72,4412.74 1038.15,4412.74 1047,4403.89 1046.42,4403.31 v2(1047.31,4398.09) ; CON6201.28@1046.64,4253.14 v2(1046.95,4252.83) ; v2(1050.06,4240.31) 1050.06,4237.83 CON6201.27@1047.07,4237.83 ; v2(1053.31,3572.09) VR2101.2@1053.31,3569.5 1070.79,3569.5 ; v2(1055.31,3663.09) 1058.31,3660.09 C10009.2@1064.72,3653.68 ; v2(1055.31,3712.09) C10008.2@1057.31,3710.09 ; v2(1056.31,3639.09) 1056.31,3642.68 v2(1064.72,3651.09) ; v2(1056.31,3688.09) 1056.31,3692.68 C10008.2@1057.31,3693.68 ; C10008.2@1057.31,3692.09 C10008.2@1057.31,3693.68 ; C10009.2@1058.31,3645.09 1064.31,3651.09 v2(1064.72,3651.09) ; 1071.42,3569.5 1070.79,3569.5 ; v2(1072.31,3640.09) 1072.31,3643.5 v2(1064.72,3651.09) ; v2(1072.31,3689.09) 1072.31,3693.5 v2(1064.72,3701.09) ; v2(1075.31,3714.09) C10008.2@1064.72,3703.5 ; v2(1093.31,3276.09) 1093.31,3300.75 CON2101.5@1105.31,3312.75 ; v2(1097.78,3370.57) 1090.51,3377.84 1090.51,3412.58 1116.61,3438.68 1122.8,3438.68 v2@1135.21,3451.09 ; v2(1105.31,3269.09) CON2101.5@1105.31,3312.75 ; v2(1111.95,3811.49) 1118.23,3810.2 1123.95,3804.48 1121.95,3802.49 C10075.2@1121.95,3801.49 ; SH1005.1@1113.95,3757.49 1113.95,3765.49 ; v2(1120.95,3989.49) 1143.55,4012.09 1233.82,4012.09 1265.31,4043.59 1265.31,4073.53 1292.87,4101.09 1327.31,4101.09 v2(1339.31,4113.09) 1350.24,4102.16 1350.24,4099.24 1357.31,4092.18 1357.31,4083.4 1367.31,4073.4 1367.31,3982.09 1457.31,3892.09 1457.31,3546.49 1507.31,3496.49 1507.31,3405.33 1488.07,3386.09 1486.32,3386.09 1483.72,3383.49 v2(1467.95,3383.49) ; v2(1123.92,4142.71) CON6201.10@1131.28,4142.9 ; v2(1124.41,4237.64) 1131.26,4237.82 CON6201.4@1131.71,4237.83 ; v2(1124.59,4095.69) 1129.95,4095.83 1131.1,4095.83 CON6201.13@1131.28,4095.66 1131.44,4095.83 v2(1138.95,4095.83) 1223.95,4095.83 v2(1234.95,4106.83) 1251.31,4106.83 1267.57,4123.09 1273.92,4129.44 1273.92,4159.71 1253.54,4180.09 1184.09,4180.09 1146.9,4142.9 CON6201.10@1137.88,4142.9 ; v2(1126.31,3304.09) 1113.76,3316.64 CON2101.5@1109.2,3316.64 CON2101.5@1105.31,3312.75 ; CON6201.7@1131.63,4190.15 CON6201.7@1131.28,4190.15 ; v2(1131.89,4284.74) v2(1131.89,4284.74) CON6201.1@1131.95,4283.96 ; v2(1136.95,4189.83) CON6201.7@1136.95,4190.15 ; v2(1137.95,4142.83) CON6201.10@1137.88,4142.9 ; v2(1137.95,4237.83) CON6201.4@1131.71,4237.83 ; v2@1138.5,3455.28 v2(1138.95,3454.83) ; v2(1149.95,4307.83) 1149.95,4320.83 v2(1171.95,4342.83) ; VR2102.2@1166.95,3580.9 v2(1166.95,3586.73) ; v2(1177.54,3569.49) 1180.31,3566.09 1191.31,3555.09 1208.31,3555.09 1215.31,3562.09 1359.31,3562.09 1433.31,3636.09 1433.31,3870.92 ; v2(1185.31,3591.09) 1191.31,3597.09 1212.31,3597.09 1222.31,3587.09 1350.31,3587.09 1404.31,3641.09 v2(1404.32,3695.74) ; SH1002.2@1186.31,3969.09 1204.86,3969.09 C10062.2@1205.59,3969.81 ; C10062.2@1204.31,3971.09 C10062.2@1205.59,3969.81 ; v2(1208.31,3337.09) CON2101.4@1227.71,3317.7 ; C10062.2@1208.31,3967.09 C10062.2@1205.59,3969.81 ; v2(1221.31,3347.09) 1227.71,3340.7 CON2101.4@1227.71,3317.7 ; CON2101.4@1227.71,3316.64 CON2101.4@1227.71,3317.7 ; C10006.2@1235.76,3664.09 1235.76,3675.09 1261.31,3700.64 v2(1261.31,3703.09) ; v2(1256.31,3737.09) C10012.2@1256.54,3740.49 ; v2(1275.31,3274.09) 1324.94,3274.09 1351.31,3300.46 1351.31,3374.43 1391.54,3414.66 v2(1391.54,3420.86) ; v2(1281.95,4308.83) 1200.69,4308.83 1189.31,4297.45 1189.31,4279.8 1146.9,4237.39 ; v2(1283.95,4379.83) 1269.47,4394.31 1269.47,4424.43 1287.71,4442.68 v2(1314.31,4442.68) ; v2(1288.08,4284.11) 1288.08,4257.62 1271.95,4241.49 1198.25,4241.49 1146.91,4190.15 CON6201.7@1136.95,4190.15 ; v2(1312.45,4051.16) 1312.51,4052.03 1311.22,4057.73 1315.01,4059.36 1315.31,4059.49 C10069.2@1314.95,4059.49 ; C10068.2@1314.95,3995.49 1314.95,3994.49 v2(1315.72,3992.2) ; C10071.2@1314.95,4016.49 v2(1314.95,4017.49) ; v2(1355.95,3835.49) 1357.54,3833.9 C10067.2@1357.54,3828.49 ; v2(1356.95,3820.49) C10067.2@1356.95,3825.9 ; C10065.2@1357.91,3930.09 1358.16,3929.84 1365.31,3922.68 v2(1365.31,3921.09) ; v2(1358.95,4398.83) 1359.21,4399.09 v2@1359.31,4399.09 ; R2138.2@1373.31,3317.09 1373.31,3373.77 1395.63,3396.09 1418.95,3396.09 1431.95,3383.09 R2137.2@1431.95,3356.72 ; v2(1381.31,3045.09) 1411.75,3045.09 v2(1428.03,3061.37) ; v2(1383.01,3910.14) 1394.09,3910.14 1433.31,3870.92 ; C2046.2@1383.31,3696.09 1399.31,3696.09 1400.3,3696.06 v2(1404.32,3695.74) ; C10004.2@1390.31,3745.09 1391.31,3746.09 v2(1393.31,3746.09) ; C10005.2@1394.31,3772.09 v2(1396.31,3772.09) ; SH1003.1@1397.31,3884.09 1397.31,3906.92 1433.31,3870.92 ; R2137.2@1401.95,3341.49 1414.83,3354.37 R2137.2@1421.6,3354.37 ; v2(1407.31,3340.09) R2137.2@1421.6,3354.37 ; v2(1424.31,3340.09) R2137.2@1424.31,3346.73 ; v2(1424.31,3353.09) R2137.2@1424.31,3354.37 ; v2(1435.31,3319.09) 1434.91,3318.68 1434.91,3336.68 1438.31,3340.09 v2(1440.31,3340.09) 1440.31,3346 1436.27,3350.05 R2137.2@1431.95,3354.37 ; v2(1440.31,3354.09) R2137.2@1440.03,3354.37 ; C10083.2@1441.31,4008.09 v2(1441.31,4009.09) ; v2(1455.31,3366.49) 1444.07,3366.49 R2137.2@1435.99,3358.41 ; v2(1456.95,3348.49) 1451.07,3354.37 R2137.2@1440.03,3354.37 ; v2(1559.31,4657.09) 1558.5,4656.28 CON6301.7@1558.5,4648.54 1560.31,4646.72 v2(1560.31,4643.09) ; v2(1625.31,3323.09) 1624.47,3323.93 1624.31,3323.93 1633.87,3333.49 1627.27,3340.09 v2(1625.31,3340.09) ; v2(1630.31,4589.09) v2@1649.31,4570.09 ; v2(1649.73,4574.2) 1647.97,4572.43 1649.31,4571.09 v2@1649.31,4570.09 ; CON6301.4@1656.93,4550.11 1656.93,4559.95 1649.31,4567.56 v2@1649.31,4570.09 ; v2(1725.95,4490.49) 1725.95,4491.72 C6310.2@1726.31,4492.09 ; v2(1768.54,4366.61) 1801.02,4399.09 1821.27,4399.09 1828.3,4392.06 1828.3,4382.12 1820.27,4374.09 1802.31,4374.09 v2(1798.31,4370.09) ; v2(1770.31,705.09) 1785.64,689.77 CON6101.11@1785.64,688.96 1787.44,688.96 v2(1801.31,675.09) ; v2(1785.31,759.09) 1785.31,766.59 CON6101.12@1785.64,766.92 v2(1785.64,774.77) ; v2(1793.65,3870.59) C3112.2@1804.65,3870.59 ; CON6101.1@1825.01,775.18 v2(1825.01,775.78) ; v2(1855.31,772.09) 1855.31,773.99 CON6101.5@1856.5,775.18 ; CON6101.6@1856.5,680.7 v2(1856.9,681.09) ; v2(1860.31,646.09) 1861.71,647.49 C6101.2@1861.95,647.49 ; v2(1884.38,4418.3) 1883.31,4418.09 R3903.2@1894.31,4418.09 ; CON6101.10@1888,680.7 v2(1888,681.4) ; v2(1916.82,4389.18) 1919.85,4386.52 PA3901.7@1920.07,4386.33 ; v2(1917.3,754.71) 1915.62,756.39 1926.14,766.92 CON6101.13@1927.37,766.92 ; v2(1919.31,775.09) CON6101.13@1927.37,767.03 ; C3260.2@1920.65,3705.59 1920.87,3705.59 1920.87,3705.81 1923.21,3703.47 v2(1923.43,3703.69) ; L3815.2@1921.31,4443.09 1921.31,4444.09 1922.31,4445.09 1922.7,4444.77 v2(1923.9,4443.78) ; v2(1923.31,696.09) 1927.37,692.03 CON6101.14@1927.37,688.96 ; v2(1929.31,761.09) 1929.31,764.97 CON6101.13@1927.37,766.92 ; R3631.2@1930.3,4614.09 1931.31,4614.09 v2(1935.31,4610.09) ; U3407.5@1930.47,4088.59 1933.13,4088.59 1939.27,4082.45 1939.27,4056.21 ; v2(1931.31,682.09) 1931.31,685.02 CON6101.14@1927.37,688.96 ; C3901.2@1934.08,4240.11 1934.08,4240.32 1934.19,4240.21 v2(1934.31,4240.07) ; v2(1934.31,774.09) 1927.37,767.15 CON6101.13@1927.37,767.03 ; v2(1939.31,699.09) 1937.5,699.09 CON6101.14@1927.37,688.96 ; v2(1968.96,3706.38) 1969.86,3706.38 C3210.2@1970.65,3705.59 ; v2@1986.48,3436.4 1986.62,3436.4 v2(1987.32,3435.7) ; v2(2000.3,4749.09) R3628.2@2002.3,4747.09 ; v1(2005.31,4654.09) U3604.3@2005.43,4654.09 ; v2(2015.31,4509.09) 2020.08,4504.32 NTC3701.2@2020.08,4504.11 2023.29,4504.11 v2(2027.31,4500.09) ; v2(2021,4318.15) 2025.11,4323.88 2025.33,4324.11 C3905.2@2026.08,4324.11 2032.31,4317.88 v2(2031.91,4312.25) ; v2(2027.31,4240.54) 2028.49,4241.7 2028.59,4241.81 2028.29,4242.11 C3906.2@2028.08,4242.11 ; v2(2029.36,4446.42) 2028.41,4447.07 2025.37,4444.03 2026.08,4443.32 C3910.2@2026.08,4439.11 ; v2(2041.93,4447.14) 2040.31,4447.09 2031.7,4442.26 C3910.2@2026.08,4439.11 ; v2(2050.31,4602.09) 2051.31,4603.09 L3612.1@2055.31,4603.09 ; C3604.2@2057.3,4702.09 v2(2058.3,4703.09) ; C3216.2@2060.65,3625.59 v2(2060.65,3625.75) ; v2(2064.62,3650.43) 2064.79,3650.59 C3215.2@2065.65,3650.59 ; v2(2064.76,3698.06) 2064.76,3700.59 C3222.2@2065.65,3700.59 ; CON6601.4@2078.02,734.06 2078.02,752.8 v2(2079.31,754.09) ; CON6601.4@2078.06,734.09 v2(2080.31,734.09) ; v2(2100.31,4506.09) 2103.57,4502.83 C3602.1@2119.95,4502.83 ; v2(2109.31,4452.09) 2115.74,4452.09 CON3802.4@2122.6,4445.23 2129.31,4438.52 v2(2129.31,4435.09) ; v2(2114.3,4646.09) 2112.3,4646.09 2112.3,4668.09 2113.3,4669.09 v2(2114.3,4673.09) ; v2(2127.31,821.09) 2129.2,819.2 CON6601.2@2129.2,810.83 2129.31,810.72 v2(2129.31,803.09) ; v2(2132.9,4016.48) 2144.51,4016.48 U3402.15@2146.09,4014.91 ; L3801.2@2135.95,4331.83 L3801.2@2136.94,4332.82 ; v2(2149.31,4975.09) 2149.31,4986.83 CON6503.1@2148.23,4987.91 2148.23,4992.01 v2(2149.31,4993.09) ; v2(2149.46,3999.07) 2151.04,3999.07 2151.04,4007.07 2151.47,4007.5 2153.12,4009.15 U3402.15@2153.12,4013.15 ; v2(2155.81,4165.65) 2175.81,4165.65 2176.67,4164.79 2190.81,4164.79 ; U3602.6@2156.3,4688.09 v2(2156.34,4688.17) ; v2@2156.3,4702.09 v2(2156.3,4704.09) ; 2156.3,4725.09 U3602.2@2156.3,4738.09 ; U3402.15@2159.62,4017.23 2155.54,4013.15 U3402.15@2153.12,4013.15 ; C6601.2@2160.95,869.83 v2(2160.95,870.73) ; v2(2196.31,4446.09) 2202.45,4446.09 CON3802.6@2203.31,4445.23 ; L3802.2@2197.95,4331.83 2197.95,4332.73 2201.31,4336.09 v2(2203.55,4338.18) ; v2(2209.31,732.09) 2211.28,734.06 CON6601.3@2211.88,734.06 2211.88,754.52 v2(2210.31,756.09) ; v2(2210.3,4659.09) L3602.2@2210.3,4660.09 ; v2(2213.27,4187.25) 2190.81,4164.79 ; U3404.3@2217.94,4112.89 2215.48,4112.89 2193.06,4135.31 2193.06,4144.63 2190.81,4146.88 2190.81,4164.79 ; v2(2223.31,4563.09) L3607.2@2223.29,4567.09 ; v2(2228.31,4190.65) 2230.81,4190.65 2240.64,4180.82 2245.46,4180.82 2258.13,4168.15 2258.13,4163.15 2258.31,4163.15 2258.31,4160.65 v2(2258.65,4149.88) ; 2337.74,3518.72 2351.75,3532.73 2351.75,3599.22 2341.94,3609.03 v2(2341.94,3618.03) ; v2(2384.06,3416.5) 2392.31,3435.85 CON3301.5@2398.96,3442.49 ; CON3301.6@2389.31,3379.09 2398.96,3369.44 CON3301.6@2398.96,3367.69 ; v2(2435.31,4290.09) 2435.31,4291.08 2434.95,4291.44 CON6401.5@2434.95,4306.31 ; CON6501.11@110.58,2046.07 CON6501.11@110.58,2047.35 ; CON6501.11@110.58,2046.07 CON6501.11@110.58,2047.35 ; CON6501.5@115.3,1760.08 CON6501.9@115.3,1831.3 ; v2(184.64,3581.19) U2301.A3@184.64,3581.77 ; v2(184.64,3581.19) 184.53,3581.38 U2301.A3@184.64,3581.77 ; v2(184.64,3581.19) U2301.A3@184.64,3581.77 ; LED2302.2@347.79,3579.09 349.55,3577.33 LED2302.2@351.02,3575.86 ; LED2302.2@348.08,3575.86 LED2302.2@351.02,3575.86 ; CON5001.5@581.93,4501.03 CON5001.5@581.93,4507.51 ; CON5001.5@581.93,4507.51 579.95,4509.49 579.95,4512.49 CON5001.5@581.93,4510.51 ; CON5001.5@581.93,4507.51 CON5001.5@581.93,4510.51 ; CON5001.5@581.93,4510.51 v2(582.31,4513.09) ; CON5001.5@581.93,4510.51 CON5001.5@581.93,4512.7 ; CON5001.5@581.93,4512.7 v2(582.31,4513.09) ; CON5001.5@581.93,4512.7 581.93,4513.47 v2(582.31,4513.09) ; CON5001.6@662.24,4501.01 661.45,4501.81 660.67,4501.81 CON5001.6@660.67,4501.03 660.67,4500.24 661.47,4500.24 CON5001.6@662.24,4501.01 ; CON5001.6@662.24,4501.01 674.54,4488.72 675.31,4489.49 667.74,4504.58 CON5001.6@667.09,4505.86 ; CON5001.6@662.24,4501.01 CON5001.6@667.09,4505.86 ; C2411.2@694.9,3450.09 C2411.2@694.91,3452.87 ; C2411.2@694.9,3450.09 C2411.2@694.91,3452.87 ; U2401.1@751.11,3504.58 750.82,3504.58 U2401.1@751.11,3504.58 ; U2401.3@751.24,3544.09 U2401.3@751.11,3543.95 U2401.3@751.24,3544.09 ; C2402.2@756.31,3467.47 v2(755.95,3467.83) 756.31,3468.19 C2402.2@756.31,3467.47 ; D2103.A@989.95,3647.26 D2103.A@994.31,3642.89 ; D2103.A@989.95,3647.26 D2103.A@994.31,3642.89 ; CON6201.27@1046.63,4237.39 CON6201.27@1047.07,4237.83 ; CON6201.27@1046.63,4237.39 CON6201.27@1047.07,4237.83 ; C10008.2@1057.31,3693.68 v2(1064.72,3701.09) ; C10008.2@1057.31,3693.68 1057.31,3700.68 v2(1064.72,3701.09) ; C10008.2@1057.31,3710.09 1063.36,3705.04 1064.72,3703.68 C10008.2@1064.72,3703.5 ; C10008.2@1057.31,3710.09 C10008.2@1064.72,3702.68 ; v2(1064.72,3651.09) C10009.2@1064.72,3653.68 ; v2(1064.72,3651.09) C10009.2@1064.72,3653.68 ; v2(1064.72,3651.09) C10009.2@1064.72,3653.68 ; v2(1064.72,3651.09) 1064.72,3611.63 1144.64,3531.72 1144.64,3460.52 v2(1138.95,3454.83) ; v2(1064.72,3701.09) C10008.2@1064.72,3702.68 ; v2(1064.72,3701.09) C10008.2@1064.72,3703.5 ; v2(1064.72,3701.09) C10008.2@1064.72,3703.5 ; C10008.2@1064.72,3702.68 C10008.2@1064.72,3703.5 ; 1070.79,3569.5 1112.64,3527.65 1112.64,3459.76 1121.31,3451.09 v2@1135.21,3451.09 ; CON6201.10@1131.28,4142.9 CON6201.10@1137.88,4142.9 ; CON6201.10@1131.28,4142.9 CON6201.10@1132.88,4142.9 ; CON6201.10@1131.28,4142.9 CON6201.10@1132.88,4142.9 ; CON6201.7@1131.28,4190.15 CON6201.7@1131.96,4190.83 ; CON6201.7@1131.28,4190.15 CON6201.7@1131.96,4190.83 ; CON6201.7@1131.28,4190.15 CON6201.7@1136.95,4190.15 ; CON6201.4@1131.28,4237.39 CON6201.4@1131.71,4237.83 ; CON6201.4@1131.28,4237.39 CON6201.4@1131.71,4237.83 ; CON6201.4@1131.28,4237.39 1146.9,4237.39 ; CON6201.4@1131.28,4237.39 1137.95,4237.39 1146.9,4237.39 ; CON6201.7@1131.96,4190.83 1136.95,4190.83 CON6201.7@1136.95,4190.15 ; CON6201.1@1131.95,4283.96 1131.53,4284.38 CON6201.1@1131.28,4284.64 CON6201.1@1131.95,4283.96 ; CON6201.10@1132.88,4142.9 CON6201.10@1137.88,4142.9 ; v2@1135.21,3451.09 v2(1138.95,3454.83) ; C10012.2@1256.45,3750.09 C10012.2@1256.54,3740.49 ; C10012.2@1256.45,3750.09 v2(1256.31,3764.09) C10012.2@1256.45,3750.09 ; C10012.2@1256.45,3750.09 C10012.2@1256.54,3740.49 ; C10067.2@1356.95,3825.9 C10067.2@1357.54,3826.49 ; C10067.2@1356.95,3825.9 C10067.2@1356.95,3827.9 ; C10067.2@1356.95,3825.9 C10067.2@1357.54,3828.49 ; C10067.2@1356.95,3827.9 C10067.2@1357.54,3828.49 ; C10067.2@1356.95,3827.9 C10067.2@1357.54,3828.49 ; C10067.2@1357.54,3826.49 C10067.2@1357.54,3828.49 ; C10067.2@1357.54,3826.49 C10067.2@1357.54,3828.49 ; C10067.2@1357.54,3826.49 1404.31,3779.72 v2(1404.32,3695.74) ; C10067.2@1357.54,3826.49 C10067.2@1357.54,3828.49 ; R2137.2@1421.6,3354.37 R2137.2@1424.31,3354.37 ; R2137.2@1424.31,3346.73 R2137.2@1431.95,3354.37 ; R2137.2@1424.31,3346.73 1427.49,3349.91 R2137.2@1431.95,3354.37 ; R2137.2@1424.31,3354.37 1424.31,3356.09 1430.23,3356.09 R2137.2@1431.95,3354.37 ; R2137.2@1424.31,3354.37 R2137.2@1431.95,3354.37 ; R2137.2@1424.31,3354.37 R2137.2@1431.95,3354.37 ; R2137.2@1431.95,3354.37 R2137.2@1440.03,3354.37 ; R2137.2@1431.95,3354.37 R2137.2@1440.03,3354.37 ; R2137.2@1431.95,3354.37 R2137.2@1435.99,3358.41 ; R2137.2@1431.95,3354.37 R2137.2@1431.95,3356.72 ; R2137.2@1431.95,3356.72 1434.8,3359.58 R2137.2@1435.99,3358.41 ; R2137.2@1435.99,3358.41 R2137.2@1440.03,3354.37 ; PA3901.7@1920.07,4386.33 PA3901.7@1919.69,4386.34 PA3901.7@1920.07,4386.33 ; CON6101.13@1927.37,766.92 CON6101.13@1927.37,767.03 ; C3910.2@2026.08,4439.11 2025.31,4438.34 C3910.2@2026.08,4439.11 ; U3402.15@2145.81,4013.15 2146.93,4014.27 U3402.15@2147.95,4014.27 ; U3402.15@2145.81,4013.15 U3402.15@2146.09,4014.91 ; U3402.15@2145.81,4013.15 U3402.15@2147.85,4013.15 ; U3402.15@2146.09,4014.91 2146.83,4014.17 U3402.15@2147.85,4013.15 ; U3402.15@2146.09,4014.91 v2(2147.95,4026.59) U3402.15@2147.95,4014.27 ; U3402.15@2147.85,4013.15 U3402.15@2147.95,4013.15 ; U3402.15@2147.95,4013.15 U3402.15@2147.95,4014.27 ; U3402.15@2147.95,4013.15 U3402.15@2153.12,4013.15 ; U3402.15@2147.95,4014.27 v2(2156.12,4014.27) U3402.15@2153.12,4013.15 ; CON6401.5@2434.95,4306.31 2434.95,4306.72 v2(2435.31,4307.09) 2435.73,4307.09 CON6401.5@2434.95,4306.31 ; C10096.2@1251.61,4379.49 v2(1251.95,4379.83) C10096.2@1251.95,4379.49 C10096.2@1251.61,4379.49
  Bottom w6: v2(1985.84,3972.92) 1985.63,3972.72 2002.25,3956.09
